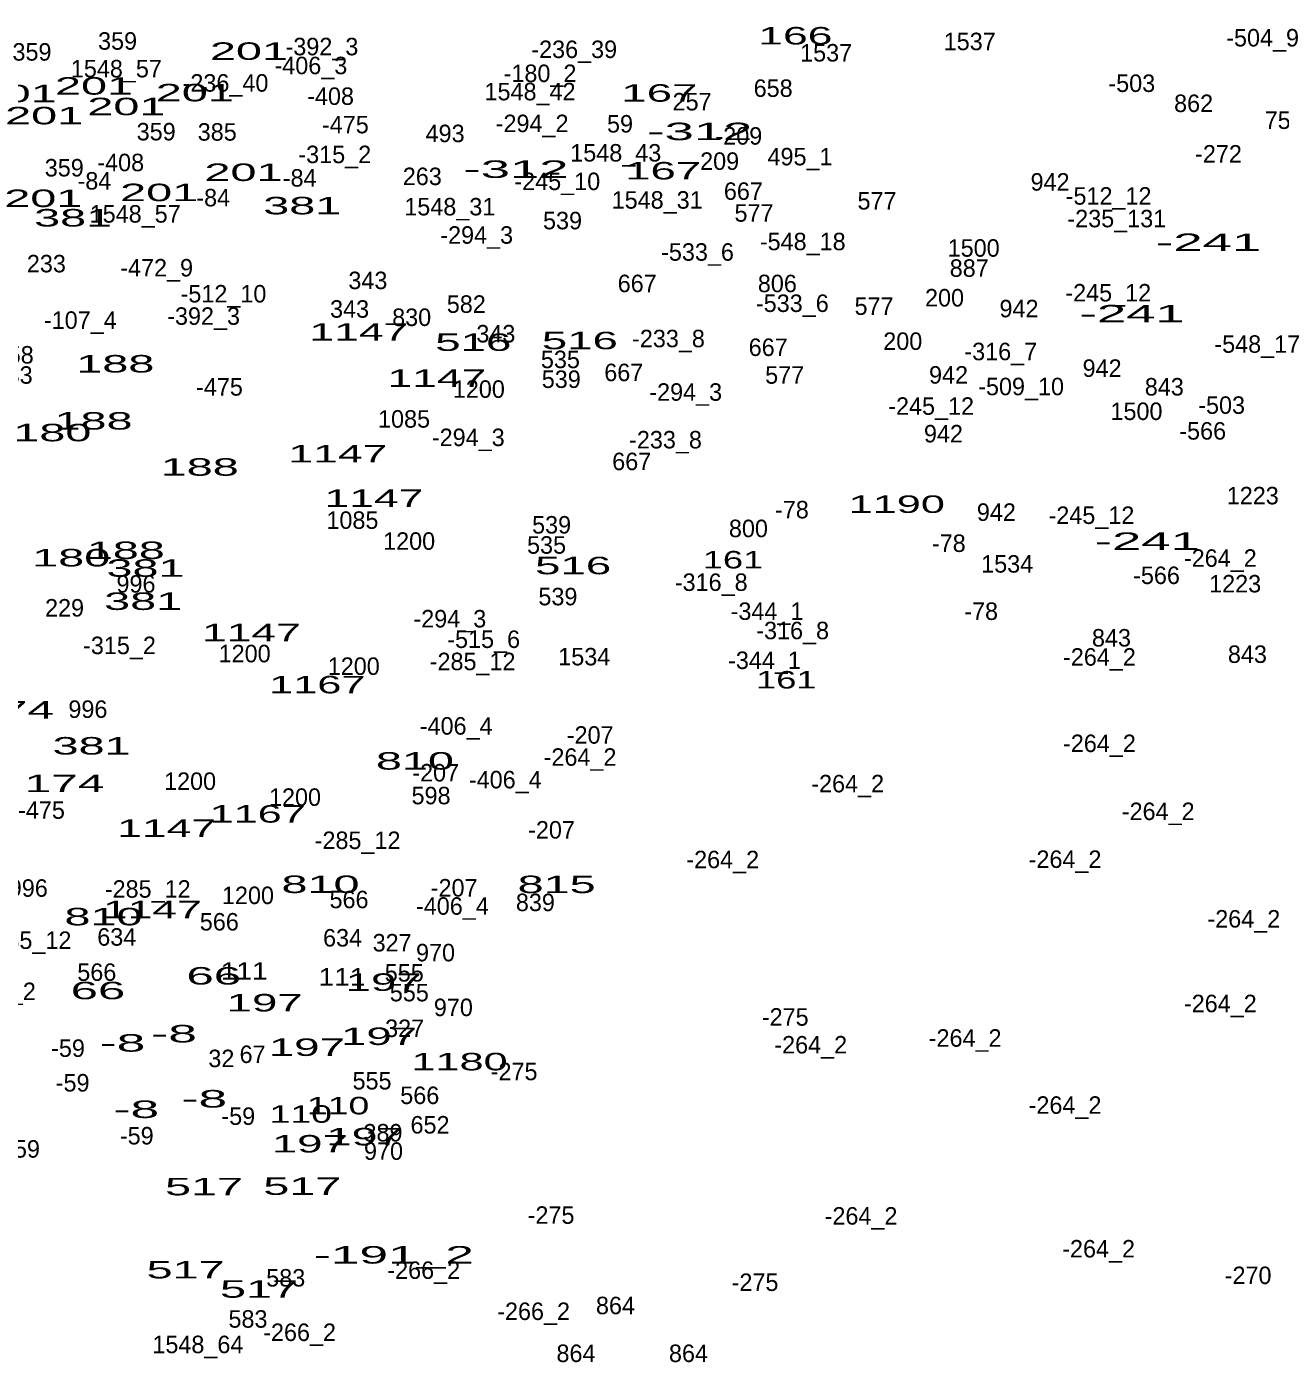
# Model space of a CAD drawing. Extents: x -660434 to -656144, y -997850 to -994016.
# Drawn here: x -658418.1 to -658131.4, y -996782 to -996476.4 of the extents above; entities that cross this region are included whole.
import ezdxf
from ezdxf.enums import TextEntityAlignment as Align

# ---------------------------------------------------------------- set-up
doc = ezdxf.new("R2010")
doc.units = 0
doc.header["$LTSCALE"] = 1.6
doc.layers.add('24', color=7, linetype='Continuous')

msp = doc.modelspace()

# ---------------------------------------------------------------- texts
at = {"layer": '24'}
for s, p in [('359', (-658397.333, -996481.7)), ('1537', (-658202.416, -996481.81)), ('-504_9', (-658135.416, -996480.96)), ('359', (-658416.913, -996484.2)), ('-392_3', (-658350.588, -996482.98)), ('-236_39', (-658292.882, -996483.61)), ('1537', (-658235.256, -996484.4)), ('1548_57', (-658397.607, -996488.04)), ('-406_3', (-658353.116, -996487.31)), ('-236_40', (-658372.645, -996491.3)), ('-180_2', (-658300.7, -996489.1)), ('-503', (-658165.339, -996491.37)), ('-408', (-658348.613, -996494.33)), ('1548_42', (-658302.987, -996493.28)), ('658', (-658247.373, -996492.5)), ('257', (-658265.913, -996495.59)), ('862', (-658151.203, -996495.96)), ('-294_2', (-658302.512, -996500.56)), ('59', (-658282.403, -996500.65)), ('750', (-658130.477, -996499.83)), ('359', (-658388.503, -996502.45)), ('385', (-658374.537, -996502.51)), ('-475', (-658345.225, -996500.83)), ('493', (-658322.417, -996502.85)), ('-209', (-658255.224, -996503.42)), ('-408', (-658396.613, -996509.5)), ('-315_2', (-658347.646, -996507.65)), ('1548_43', (-658283.377, -996507.29)), ('-209', (-658260.504, -996509.19)), ('495_1', (-658241.228, -996508.16)), ('-272', (-658145.511, -996507.52)), ('359', (-658409.523, -996510.7)), ('-84', (-658355.679, -996513.02)), ('263', (-658327.633, -996512.67)), ('-84', (-658402.629, -996513.7)), ('-245_10', (-658296.753, -996513.82)), ('667', (-658254.183, -996516.05)), ('942', (-658184.027, -996513.94)), ('-84', (-658375.459, -996517.54)), ('1548_31', (-658273.906, -996518.07)), ('577', (-658223.619, -996518.26)), ('-512_12', (-658170.649, -996517.15)), ('1548_57', (-658393.307, -996521.26)), ('1548_31', (-658321.336, -996519.61)), ('577', (-658251.749, -996521.05)), ('539', (-658295.553, -996522.79)), ('-235_131', (-658168.769, -996522.33)), ('-294_3', (-658315.192, -996526.09)), ('-548_18', (-658240.609, -996527.58)), ('-533_6', (-658264.678, -996529.98)), ('1500', (-658201.508, -996529.06)), ('233', (-658413.617, -996532.64)), ('-472_9', (-658388.398, -996533.58)), ('887', (-658202.523, -996533.66)), ('343', (-658340.081, -996536.48)), ('667', (-658278.473, -996537.17)), ('806', (-658246.417, -996537.18)), ('-512_10', (-658373.113, -996539.53)), ('200', (-658208.175, -996540.44)), ('-245_12', (-658170.729, -996539.3)), ('343', (-658344.261, -996543.01)), ('582', (-658317.567, -996541.9)), ('-533_6', (-658242.988, -996541.7)), ('577', (-658224.289, -996542.37)), ('942', (-658191.137, -996542.92)), ('-107_4', (-658405.86, -996545.56)), ('-392_3', (-658377.658, -996544.64)), ('830', (-658330.061, -996544.91)), ('343', (-658310.801, -996548.67)), ('-233_8', (-658271.322, -996549.77)), ('667', (-658248.513, -996551.77)), ('200', (-658217.725, -996550.38)), ('-316_7', (-658195.307, -996552.74)), ('-548_17', (-658136.635, -996551.04)), ('1548_58', (-658426.922, -996553.5)), ('535', (-658296.037, -996554.55)), ('233', (-658421.217, -996558.12)), ('667', (-658281.543, -996557.53)), ('577', (-658244.739, -996558.12)), ('942', (-658207.257, -996558.09)), ('942', (-658172.127, -996556.55)), ('-475', (-658374.025, -996560.84)), ('1200', (-658314.698, -996561.34)), ('539', (-658295.843, -996559.08)), ('-509_10', (-658190.659, -996560.75)), ('843', (-658157.901, -996560.81)), ('-294_3', (-658267.382, -996562.01)), ('-503', (-658144.789, -996565.01)), ('-245_12', (-658211.239, -996565.23)), ('1500', (-658164.268, -996566.42)), ('1085', (-658331.804, -996568.17)), ('-566', (-658149.125, -996570.9)), ('-294_3', (-658317.112, -996572.38)), ('-233_8', (-658272.002, -996572.92)), ('942', (-658208.417, -996571.54)), ('667', (-658279.723, -996577.89)), ('1223', (-658137.67, -996585.71)), ('-78', (-658243.081, -996588.92)), ('1085', (-658343.614, -996591.32)), ('539', (-658298.053, -996592.39)), ('942', (-658196.317, -996589.49)), ('-245_12', (-658174.569, -996590.2)), ('800', (-658253.035, -996593.22)), ('1200', (-658330.638, -996596.11)), ('535', (-658299.207, -996597)), ('-78', (-658207.201, -996596.6)), ('1534', (-658193.844, -996601.33)), ('-264_2', (-658145.092, -996600)), ('-566', (-658159.685, -996603.94)), ('996', (-658393.123, -996605.9)), ('-316_8', (-658261.542, -996605.52)), ('1223', (-658141.7, -996605.87)), ('539', (-658296.613, -996608.81)), ('229', (-658409.463, -996611.38)), ('-294_3', (-658321.332, -996613.87)), ('-344_1', (-658248.775, -996612.15)), ('-78', (-658199.801, -996612.16)), ('-316_8', (-658242.912, -996616.57)), ('-315_2', (-658396.896, -996619.98)), ('-515_6', (-658313.592, -996618.57)), ('843', (-658169.991, -996618.24)), ('1200', (-658368.268, -996621.85)), ('1534', (-658290.584, -996622.55)), ('-264_2', (-658172.742, -996622.62)), ('843', (-658138.891, -996621.99)), ('1200', (-658343.308, -996624.73)), ('-285_12', (-658316.125, -996623.65)), ('-344_1', (-658249.355, -996623.38)), ('996', (-658404.123, -996634.57)), ('-406_4', (-658319.88, -996638.4)), ('-207', (-658289.234, -996640.47)), ('-264_2', (-658172.742, -996642.38)), ('-264_2', (-658291.552, -996645.52)), ('-207', (-658324.564, -996649.11)), ('1200', (-658380.748, -996651.04)), ('-406_4', (-658308.65, -996650.69)), ('-264_2', (-658230.332, -996651.6)), ('1200', (-658356.748, -996654.69)), ('598', (-658325.623, -996654.33)), ('-475', (-658414.735, -996657.65)), ('-264_2', (-658159.302, -996657.94)), ('-207', (-658298.074, -996662.17)), ('-285_12', (-658342.435, -996664.56)), ('-264_2', (-658180.612, -996668.89)), ('-264_2', (-658258.912, -996668.96)), ('996', (-658417.753, -996675.49)), ('-285_12', (-658390.435, -996675.7)), ('1200', (-658367.508, -996677.16)), ('-207', (-658320.344, -996675.43)), ('566', (-658344.388, -996678.11)), ('-406_4', (-658320.75, -996679.6)), ('839', (-658301.763, -996678.77)), ('566', (-658374.058, -996683.2)), ('-264_2', (-658139.712, -996682.53)), ('634', (-658397.517, -996686.68)), ('634', (-658345.867, -996686.87)), ('-285_12', (-658417.705, -996687.42)), ('327', (-658334.533, -996688)), ('970', (-658324.602, -996690.26)), ('566', (-658402.088, -996694.73)), ('555', (-658331.757, -996694.89)), ('-315_2', (-658424.356, -996699.12)), ('555', (-658330.597, -996699.41)), ('-264_2', (-658145.092, -996701.9)), ('970', (-658320.522, -996702.79)), ('-275', (-658244.611, -996704.98)), ('327', (-658331.673, -996707.57)), ('-264_2', (-658238.782, -996711.34)), ('-264_2', (-658203.462, -996709.8)), ('-59', (-658408.67, -996712.12)), ('32', (-658373.597, -996714.47)), ('67', (-658366.448, -996713.52)), ('-275', (-658306.631, -996717.46)), ('-59', (-658407.61, -996720.04)), ('555', (-658339.127, -996719.57)), ('566', (-658328.208, -996722.91)), ('-264_2', (-658180.612, -996725.14)), ('-59', (-658369.72, -996727.68)), ('652', (-658325.863, -996729.65)), ('-59', (-658392.94, -996732.15)), ('389', (-658336.623, -996731.47)), ('-59', (-658418.95, -996735.17)), ('970', (-658336.502, -996735.67)), ('-275', (-658298.181, -996750.31)), ('-264_2', (-658227.272, -996750.49)), ('-264_2', (-658172.932, -996758.01)), ('-266_2', (-658327.303, -996762.91)), ('583', (-658358.867, -996764.66)), ('-275', (-658251.521, -996765.67)), ('-270', (-658138.734, -996764.09)), ('-266_2', (-658302.173, -996772.31)), ('864', (-658283.447, -996770.99)), ('583', (-658367.507, -996774.07)), ('-266_2', (-658355.703, -996777.12)), ('1548_64', (-658378.962, -996779.9)), ('864', (-658292.477, -996781.93)), ('864', (-658266.747, -996781.93))]:
    msp.add_text(s, height=4, dxfattribs=at).set_placement(p, align=Align.CENTER)
for s, width, p in [('166', 1.9, (-658242.297, -996480.5)), ('201', 2, (-658367.284, -996484.02)), ('201', 2, (-658420.184, -996493.72)), ('201', 2, (-658402.714, -996491.99)), ('201', 2, (-658379.664, -996493.52)), ('167', 1.95, (-658273.397, -996493.6)), ('201', 2, (-658395.314, -996496.69)), ('201', 2, (-658414.134, -996498.78)), ('-312', 2.25, (-658264.171, -996502.39)), ('201', 2, (-658368.534, -996511.74)), ('-312', 2.25, (-658306.231, -996511.03)), ('167', 1.95, (-658272.537, -996511.38)), ('201', 2, (-658414.324, -996517.7)), ('201', 2, (-658387.824, -996516.35)), ('381', 2, (-658407.507, -996522.15)), ('381', 2, (-658355.087, -996519.37)), ('-241', 2.25, (-658147.806, -996527.76)), ('-241', 2.25, (-658165.286, -996544.08)), ('1147', 1.9, (-658342.145, -996548.28)), ('516', 1.95, (-658315.973, -996550.61)), ('516', 1.95, (-658291.593, -996550.23)), ('188', 2, (-658397.847, -996555.55)), ('1147', 1.9, (-658324.285, -996558.84)), ('188', 2, (-658402.837, -996568.61)), ('180', 2, (-658412.254, -996571.29)), ('1147', 1.9, (-658346.945, -996576.13)), ('188', 2, (-658378.547, -996579.16)), ('1147', 1.9, (-658338.685, -996586.3)), ('1190', 1.85, (-658219.095, -996587.67)), ('188', 2, (-658395.447, -996598.22)), ('-241', 2.25, (-658161.826, -996596.14)), ('180', 2, (-658407.934, -996599.91)), ('161', 1.55, (-658256.559, -996600.37)), ('381', 2, (-658390.947, -996602.28)), ('516', 1.95, (-658293.133, -996601.71)), ('381', 2, (-658391.477, -996609.87)), ('1147', 1.9, (-658366.725, -996617.04)), ('1167', 1.85, (-658351.643, -996628.95)), ('161', 1.55, (-658244.369, -996627.84)), ('174', 2.05, (-658420.988, -996634.73)), ('381', 2, (-658403.277, -996642.95)), ('810', 2, (-658329.314, -996646.4)), ('174', 2.05, (-658409.468, -996651.54)), ('1167', 1.85, (-658365.283, -996658.53)), ('1147', 1.9, (-658386.115, -996661.79)), ('810', 2, (-658350.914, -996674.63)), ('815', 2, (-658296.897, -996674.65)), ('1147', 1.9, (-658389.375, -996680.41)), ('810', 2, (-658400.554, -996682.03)), ('66', 2.1, (-658375.331, -996695.57)), ('111', 1.2, (-658368.37, -996694.46)), ('111', 1.2, (-658346, -996695.8)), ('66', 2.1, (-658401.821, -996698.93)), ('197', 1.95, (-658336.467, -996697.01)), ('197', 1.95, (-658363.677, -996701.72)), ('-8', 2.2, (-658396.224, -996710.92)), ('-8', 2.2, (-658384.414, -996708.81)), ('197', 1.95, (-658337.517, -996709.4)), ('197', 1.95, (-658354.037, -996711.9)), ('1180', 1.85, (-658319.11, -996715.2)), ('-8', 2.2, (-658377.504, -996723.7)), ('-8', 2.2, (-658393.054, -996726.1)), ('110', 1.6, (-658346.89, -996725.27)), ('110', 1.6, (-658355.43, -996727.19)), ('197', 1.95, (-658340.877, -996732.36)), ('197', 1.95, (-658353.357, -996733.99)), ('517', 2, (-658377.543, -996743.79)), ('517', 2, (-658355.083, -996743.69)), ('-191_2', 2.2, (-658334.153, -996759.41)), ('517', 2, (-658381.773, -996762.8)), ('517', 2, (-658364.973, -996767.22))]:
    msp.add_text(s, height=4, dxfattribs=dict(at, width=width)).set_placement(p, align=Align.CENTER)

doc.saveas('drawing.dxf')
